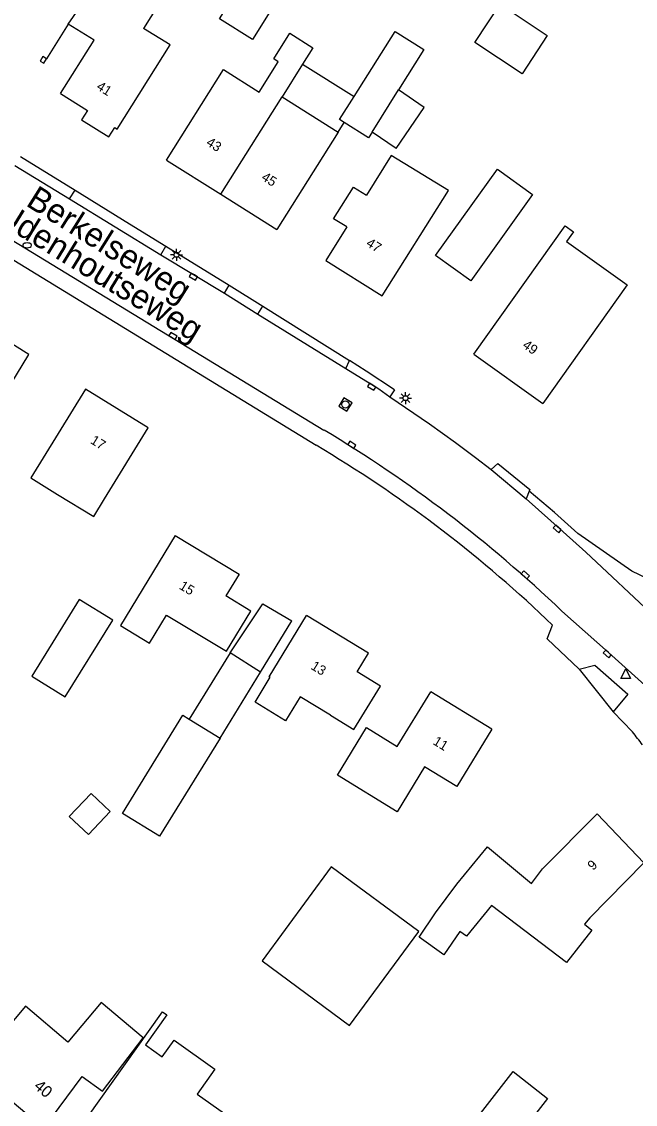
# Model space of a CAD drawing. Extents: x 136000 to 141000, y 400494 to 402006.
# Drawn here: x 137848.1 to 137911.7, y 401752.7 to 401864.8 of the extents above; entities that cross this region are included whole.
import ezdxf

# ---------------------------------------------------------------- set-up
doc = ezdxf.new("R2010")
doc.units = 0
for name, color, linetype in [('gg-afsc-erfafscheiding', 7, 'Continuous'), ('gg-afsc-muur', 7, 'Continuous'), ('gg-anno-huisnummerreeks BGT', 7, 'Continuous'), ('gg-anno-openbare ruimte label', 7, 'Continuous'), ('gg-bbg-bijgebouw', 7, 'Continuous'), ('gg-bbg-gedigitaliseerde bebouwing', 7, 'Continuous'), ('gg-bbg-gedigitaliseerde bijgebouw', 7, 'Continuous'), ('gg-bbg-hoofdgebouw', 7, 'Continuous'), ('gg-bbg-luifel en loopbrug', 7, 'Continuous'), ('gg-bbg-tussenscheiding', 7, 'Continuous'), ('gg-knt-verharding', 7, 'Continuous'), ('gg-knt-verharding nz', 7, 'Continuous'), ('gt-anno-plantopografie huisnummer', 7, 'Continuous'), ('gt-bbg-plantopografie pand', 7, 'Continuous'), ('gt-grn-vlakafsluiter', 7, 'Continuous'), ('gt-symb-brandkraan', 7, 'Continuous'), ('gt-symb-kolk', 7, 'Continuous'), ('gt-symb-lichtmast', 7, 'Continuous'), ('gt-symb-rioolschacht', 7, 'Continuous'), ('gt-symb-waterafsluiter', 7, 'Continuous')]:
    doc.layers.add(name, color=color, linetype=linetype)

# ---------------------------------------------------------------- blocks, each defined once
blk = doc.blocks.new('gt0-BR')
at = {"layer": 'gt-symb-brandkraan'}
for centre, radius, start, end in [((-0.24, 0), 0.206, 107.5669, 252.4331), ((0.6, -2.66), 3, 106.892, 107.5669), ((0, -0.69), 0.938, 73.108, 106.892), ((-0.6, -2.66), 3, 72.4331, 73.108), ((0.24, 0), 0.206, 287.567, 72.4331), ((0.6, 2.66), 3, 252.4331, 253.108), ((0, 0.69), 0.938, 253.108, 286.8921), ((-0.6, 2.66), 3, 286.8921, 287.567)]:
    blk.add_arc(centre, radius, start, end, dxfattribs=at)
blk = doc.blocks.new('gt0-KOLK')
at = {"layer": 'gt-symb-kolk'}
blk.add_lwpolyline([(0, 0), (0.38, 0), (0.38, 0.4), (-0.38, 0.4), (-0.38, 0), (0, 0)], dxfattribs=at)
blk = doc.blocks.new('gt0-LMAST')
at = {"layer": 'gt-symb-lichtmast'}
for p, q in [((-0.18, 0.17), (-0.45, 0.44)), ((-0.01, 0.25), (-0.01, 0.62)), ((0.17, 0.17), (0.44, 0.44)), ((-0.26, 0), (-0.63, 0)), ((-0.18, -0.18), (-0.45, -0.45)), ((-0.01, -0.25), (-0.01, -0.63)), ((0.44, -0.45), (0.17, -0.18)), ((0.24, 0), (0.62, 0))]:
    blk.add_line(p, q, dxfattribs=at)
blk.add_circle((-0.01, 0), 0.25, dxfattribs=at)
blk = doc.blocks.new('gt0-RS')
at = {"layer": 'gt-symb-rioolschacht'}
blk.add_lwpolyline([(-0.5, -0.5), (0.5, -0.5), (0.5, 0.5), (-0.5, 0.5)], close=True, dxfattribs=at)
blk.add_circle((0, 0), 0.375, dxfattribs=at)
blk = doc.blocks.new('gt0-WAFSL')
at = {"layer": 'gt-symb-waterafsluiter'}
for p, q in [((-0.5, -0.33), (0, 0.67)), ((0, 0.67), (0.5, -0.33)), ((0.5, -0.33), (-0.5, -0.33))]:
    blk.add_line(p, q, dxfattribs=at)

msp = doc.modelspace()

# ---------------------------------------------------------------- linework, layer by layer
at = {"layer": 'gg-afsc-erfafscheiding'}
for p, q in [((137848.02, 401850.86), (137853.68, 401847.37)), ((137853.68, 401847.37), (137859.32, 401843.9)), ((137859.32, 401843.9), (137863.1, 401841.58)), ((137863.1, 401841.58), (137869.64, 401837.55)), ((137869.64, 401837.55), (137873.13, 401835.37)), ((137873.13, 401835.37), (137882.12, 401829.72)), ((137905.91, 401797.79), (137909.42, 401793.38))]:
    msp.add_line(p, q, dxfattribs=at)
for points in [[(137886.78, 401826.7), (137883.86, 401828.63), (137882.12, 401829.72)], [(137913.02, 401807.13), (137911.36, 401807.91), (137905.77, 401811.83), (137903.34, 401813.99), (137900.74, 401816.21)]]:
    msp.add_lwpolyline(points, dxfattribs=at)
at = {"layer": 'gg-afsc-muur'}
msp.add_line((137852.98, 401864.57), (137850.72, 401860.97), dxfattribs=at)
msp.add_lwpolyline([(137850.72, 401860.97), (137850.35, 401861.2), (137850.07, 401860.74), (137850.43, 401860.51), (137850.72, 401860.97)], dxfattribs=at)
at = {"layer": 'gg-bbg-bijgebouw'}
for p, q in [((137884.07, 401852.78), (137881.57, 401854.36)), ((137884.46, 401853.36), (137884.07, 401852.78)), ((137886.94, 401851.68), (137884.46, 401853.36)), ((137872.91, 401797.47), (137869.76, 401799.48))]:
    msp.add_line(p, q, dxfattribs=at)
for points in [[(137894.68, 401837.98), (137891.04, 401840.59), (137897.44, 401849.53), (137901.08, 401846.92), (137894.68, 401837.98)], [(137899.07, 401756.12), (137902.64, 401753.32), (137894.52, 401742.91), (137890.95, 401745.7), (137899.07, 401756.12)]]:
    msp.add_lwpolyline(points, dxfattribs=at)
at = {"layer": 'gg-bbg-gedigitaliseerde bebouwing'}
for p, q in [((137877.25, 401860.42), (137875.13, 401857.03)), ((137863.14, 401850.49), (137869.05, 401859.87)), ((137875.13, 401857.03), (137880.94, 401853.36)), ((137856.74, 401815.41), (137861.26, 401822.76))]:
    msp.add_line(p, q, dxfattribs=at)
for points in [[(137852.98, 401864.57), (137862.47, 401878.22), (137865.87, 401876.08), (137862.51, 401870.73), (137864.24, 401869.64), (137860.78, 401864.12)], [(137858.05, 401853.69), (137863.52, 401862.4), (137860.78, 401864.12)], [(137869.05, 401859.87), (137872.76, 401857.53), (137874.74, 401860.66), (137874.27, 401860.95), (137875.95, 401863.61), (137878.32, 401862.12), (137877.25, 401860.42)], [(137894.99, 401830.38), (137904.45, 401843.68), (137905.32, 401843.07), (137904.6, 401842.05), (137910.9, 401837.57), (137902.16, 401825.28)], [(137854.76, 401826.77), (137849.11, 401817.58), (137851.87, 401815.88)], [(137851.87, 401815.88), (137855.62, 401813.58), (137856.74, 401815.41)], [(137864.04, 401811.62), (137858.4, 401802.29), (137861.4, 401800.47), (137863.16, 401803.37), (137869.38, 401799.64)], [(137880.14, 401793.02), (137882.58, 401791.53), (137885.33, 401796.02)], [(137880.14, 401793.02), (137877.02, 401794.93), (137875.49, 401792.44), (137872.33, 401794.38)], [(137904.61, 401767.4), (137896.84, 401773.32), (137894.25, 401770.14), (137893.54, 401770.62), (137891.89, 401768.22), (137889.32, 401770.05), (137891.02, 401772.56), (137893.22, 401775.54), (137896.42, 401779.38)]]:
    msp.add_lwpolyline(points, dxfattribs=at)
at = {"layer": 'gg-bbg-gedigitaliseerde bijgebouw'}
for p, q in [((137869.76, 401799.48), (137865.52, 401792.6)), ((137868.7, 401790.64), (137872.91, 401797.47))]:
    msp.add_line(p, q, dxfattribs=at)
for points in [[(137868.65, 401865.11), (137874.21, 401874), (137877.63, 401871.86), (137872.07, 401862.97), (137868.65, 401865.11)], [(137882.59, 401857.05), (137886.85, 401863.8), (137889.83, 401861.92), (137887.2, 401857.74)], [(137881.57, 401854.36), (137881.09, 401854.67), (137882.59, 401857.05)], [(137886.94, 401851.68), (137889.84, 401855.94), (137887.2, 401857.74)], [(137857.58, 401802.85), (137854.12, 401804.99), (137849.2, 401797.05), (137852.66, 401794.91), (137857.58, 401802.85)], [(137868.7, 401790.64), (137862.43, 401780.48), (137858.59, 401782.85), (137864.86, 401793.01), (137865.52, 401792.6)], [(137853.08, 401782.52), (137855.34, 401784.91), (137857.32, 401783.04), (137855.06, 401780.65), (137853.08, 401782.52)], [(137873.06, 401767.6), (137882.13, 401760.91), (137889.29, 401770.62), (137880.21, 401777.31), (137873.06, 401767.6)]]:
    msp.add_lwpolyline(points, dxfattribs=at)
at = {"layer": 'gg-bbg-hoofdgebouw'}
for p, q in [((137880.94, 401853.36), (137874.58, 401843.3)), ((137863.14, 401850.49), (137868.79, 401846.94)), ((137868.79, 401846.94), (137874.58, 401843.3)), ((137881.84, 401843.58), (137879.66, 401840.09)), ((137879.66, 401840.09), (137885.51, 401836.43)), ((137848.9, 401830.37), (137842.39, 401834.37)), ((137894.99, 401830.38), (137902.16, 401825.28)), ((137861.26, 401822.76), (137854.76, 401826.77)), ((137896.85, 401791.56), (137890.53, 401795.43))]:
    msp.add_line(p, q, dxfattribs=at)
for points in [[(137852.19, 401857.37), (137855.66, 401862.89), (137852.98, 401864.57)], [(137852.19, 401857.37), (137854.97, 401855.62), (137854.36, 401854.65), (137857.18, 401852.88), (137857.8, 401853.85), (137858.05, 401853.69)], [(137885.51, 401836.43), (137892.36, 401847.32), (137886.45, 401850.96), (137883.89, 401846.85)], [(137881.84, 401843.58), (137880.47, 401844.41), (137882.54, 401847.69), (137883.89, 401846.85)], [(137842.39, 401834.37), (137835.85, 401823.81), (137839.62, 401821.49), (137840.46, 401822.87), (137843.25, 401821.16), (137848.9, 401830.37)], [(137864.04, 401811.62), (137870.67, 401807.61), (137869.31, 401805.36)], [(137869.38, 401799.64), (137871.9, 401803.8), (137869.31, 401805.36)], [(137872.33, 401794.38), (137873.9, 401796.94), (137873.8, 401797), (137877.67, 401803.35)], [(137885.33, 401796.02), (137882.9, 401797.51), (137884.07, 401799.43), (137877.67, 401803.35)], [(137896.85, 401791.56), (137893.22, 401785.63), (137889.9, 401787.66), (137887.06, 401783.02), (137880.87, 401786.8), (137883.89, 401791.73), (137887.07, 401789.78), (137890.53, 401795.43)], [(137896.42, 401779.38), (137900.99, 401775.58), (137902.13, 401777.11), (137907.76, 401782.81), (137912.62, 401777.72), (137907, 401772.04), (137906.45, 401771.37), (137907.24, 401770.75), (137904.61, 401767.4)]]:
    msp.add_lwpolyline(points, dxfattribs=at)
at = {"layer": 'gg-bbg-luifel en loopbrug'}
for p, q in [((137877.25, 401860.42), (137882.59, 401857.05)), ((137880.94, 401853.36), (137881.57, 401854.36)), ((137872.91, 401797.47), (137876.14, 401802.77))]:
    msp.add_line(p, q, dxfattribs=at)
for points in [[(137895.1, 401862.66), (137897.72, 401866.61), (137902.61, 401863.37), (137899.99, 401859.42), (137895.1, 401862.66)], [(137869.76, 401799.48), (137873.12, 401804.56), (137876.14, 401802.77)]]:
    msp.add_lwpolyline(points, dxfattribs=at)
at = {"layer": 'gg-bbg-tussenscheiding'}
for p, q in [((137868.79, 401846.94), (137875.13, 401857.03)), ((137884.46, 401853.36), (137887.2, 401857.74)), ((137865.52, 401792.6), (137868.7, 401790.64))]:
    msp.add_line(p, q, dxfattribs=at)
at = {"layer": 'gg-knt-verharding'}
for p, q in [((137817.29, 401860.37), (137879.47, 401822.53)), ((137853.11, 401846.47), (137853.68, 401847.37)), ((137844.09, 401842.11), (137878.65, 401820.96)), ((137862.58, 401840.68), (137863.1, 401841.58)), ((137869.15, 401836.72), (137869.64, 401837.55)), ((137872.62, 401834.55), (137873.13, 401835.37)), ((137881.72, 401828.92), (137882.12, 401829.72)), ((137886.78, 401826.7), (137886.29, 401825.98)), ((137896.79, 401818.46), (137897.49, 401819.06)), ((137900.79, 401816.37), (137900.74, 401816.21)), ((137900.74, 401816.21), (137900.43, 401815.4)), ((137906.59, 401809.89), (137913.82, 401803.14)), ((137902.5, 401802.97), (137903.16, 401802.35)), ((137905.91, 401797.79), (137907.54, 401798.21)), ((137909.42, 401793.38), (137911.43, 401791.28))]:
    msp.add_line(p, q, dxfattribs=at)
for points in [[(137886.29, 401825.98), (137890.42, 401823.18), (137893.1, 401821.25), (137895.16, 401819.71), (137896.79, 401818.46)], [(137900.43, 401815.4), (137904.25, 401812.01), (137906.59, 401809.89)], [(137917.17, 401792.11), (137908.96, 401799.5), (137904.11, 401803.8)], [(137905.91, 401797.79), (137902.61, 401800.93), (137903.16, 401802.35)], [(137907.54, 401798.21), (137910.96, 401795.19), (137909.42, 401793.38)]]:
    msp.add_lwpolyline(points, dxfattribs=at)
for centre, radius, start, end in [((137808.09, 401703.06), 139.17, 46.372, 59.1403), ((137811.06, 401706.56), 132.87, 46.5145, 59.4234), ((137900.31, 401781.66), 14.7, 34.2596, 40.8611)]:
    msp.add_arc(centre, radius, start, end, dxfattribs=at)
at = {"layer": 'gg-knt-verharding nz'}
for p, q in [((137847.44, 401849.92), (137853.11, 401846.47)), ((137853.11, 401846.47), (137862.58, 401840.68)), ((137862.58, 401840.68), (137869.15, 401836.72)), ((137869.15, 401836.72), (137872.62, 401834.55)), ((137872.62, 401834.55), (137881.72, 401828.92)), ((137896.79, 401818.46), (137900.43, 401815.4))]:
    msp.add_line(p, q, dxfattribs=at)
msp.add_lwpolyline([(137881.72, 401828.92), (137885.14, 401826.81), (137886.29, 401825.98)], dxfattribs=at)
at = {"layer": 'gt-bbg-plantopografie pand'}
for points in [[(137856.51, 401754.08), (137860.73, 401759.61), (137856.4, 401763.27), (137852.94, 401759.16), (137848.53, 401762.88), (137842.08, 401755.23), (137845.04, 401752.74), (137846.06, 401753.95), (137850.44, 401750.26), (137854.43, 401755.62), (137856.51, 401754.08)], [(137863.95, 401759.37), (137868.17, 401756.37), (137866.35, 401753.8), (137870.59, 401750.79), (137863.67, 401741.08), (137859.33, 401744.17), (137858.76, 401743.37), (137858.35, 401743.66), (137860.8, 401747.09), (137854.9, 401751.29), (137862.74, 401762.31), (137863.18, 401762), (137860.97, 401758.89), (137862.72, 401757.64), (137863.95, 401759.37)]]:
    msp.add_lwpolyline(points, dxfattribs=at)
at = {"layer": 'gt-grn-vlakafsluiter'}
msp.add_line((137897.49, 401819.06), (137900.79, 401816.37), dxfattribs=at)

# ---------------------------------------------------------------- block references
at = {"layer": 'gt-symb-brandkraan'}
msp.add_blockref('gt0-BR', (137848.72, 401841.66), dxfattribs=at)
at = {"layer": 'gt-symb-kolk'}
for p, rotation in [((137866.05, 401838.59), 148.90477105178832), ((137863.73, 401832.11), -31.543673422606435), ((137884.52, 401827.19), 148.2597978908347), ((137882.25, 401820.83), -32.00538320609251), ((137903.77, 401812.45), 138.4086815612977), ((137900.2, 401807.4), -41.99999127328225), ((137908.96, 401799.5), 138.00858869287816)]:
    msp.add_blockref('gt0-KOLK', p, dxfattribs=dict(at, rotation=rotation))
at = {"layer": 'gt-symb-lichtmast'}
for p in [(137864.2, 401840.67), (137887.93, 401825.84)]:
    msp.add_blockref('gt0-LMAST', p, dxfattribs=at)
at = {"layer": 'gt-symb-rioolschacht', "rotation": -32.00538320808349}
msp.add_blockref('gt0-RS', (137881.69, 401825.18), dxfattribs=at)
at = {"layer": 'gt-symb-waterafsluiter'}
msp.add_blockref('gt0-WAFSL', (137910.74, 401797.15), dxfattribs=at)

# ---------------------------------------------------------------- texts
at = {"layer": 'gg-anno-huisnummerreeks BGT'}
for s, rotation, p in [('41', 327.8, (137855.82, 401857.87)), ('43', 327.9, (137867.19, 401852.08)), ('45', 327.9, (137872.91, 401848.48)), ('47', 328, (137883.76, 401841.65)), ('49', 324.6, (137899.96, 401831.14)), ('17', 328.3, (137855.19, 401821.22)), ('15', 328.8, (137864.39, 401806.15)), ('13', 328.5, (137878.03, 401797.85)), ('11', 328.5, (137890.68, 401790.06)), ('9', 43.7, (137907.35, 401776.89))]:
    msp.add_text(s, height=1, rotation=rotation, dxfattribs=at).set_placement(p)
at = {"layer": 'gg-anno-openbare ruimte label'}
for s, rotation, p in [('Berkelseweg', 327.9, (137848.48, 401845.83)), ('Udenhoutseweg', 328.5, (137845.32, 401844.21))]:
    msp.add_text(s, height=2.5, rotation=rotation, dxfattribs=at).set_placement(p)
at = {"layer": 'gt-anno-plantopografie huisnummer'}
msp.add_text('40', height=1.2, rotation=319.8793, dxfattribs=at).set_placement((137849.33, 401754.47))

doc.saveas('drawing.dxf')
